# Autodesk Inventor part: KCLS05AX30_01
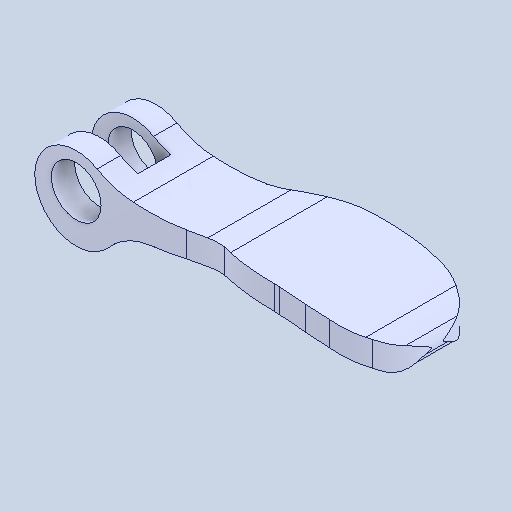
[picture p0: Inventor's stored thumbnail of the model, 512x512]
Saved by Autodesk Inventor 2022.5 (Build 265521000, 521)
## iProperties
Created: 2024-08
Part Number: KCLS05AX30_01
Material: 一般
Document SubType Name: Modeling
Designer: ImaoCorp
Density: 1 g/cm^3
Appearance: 既定
Author: ImaoCorp
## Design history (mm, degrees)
feature "KCLS05AX30_01"
node "ソリッド1"
